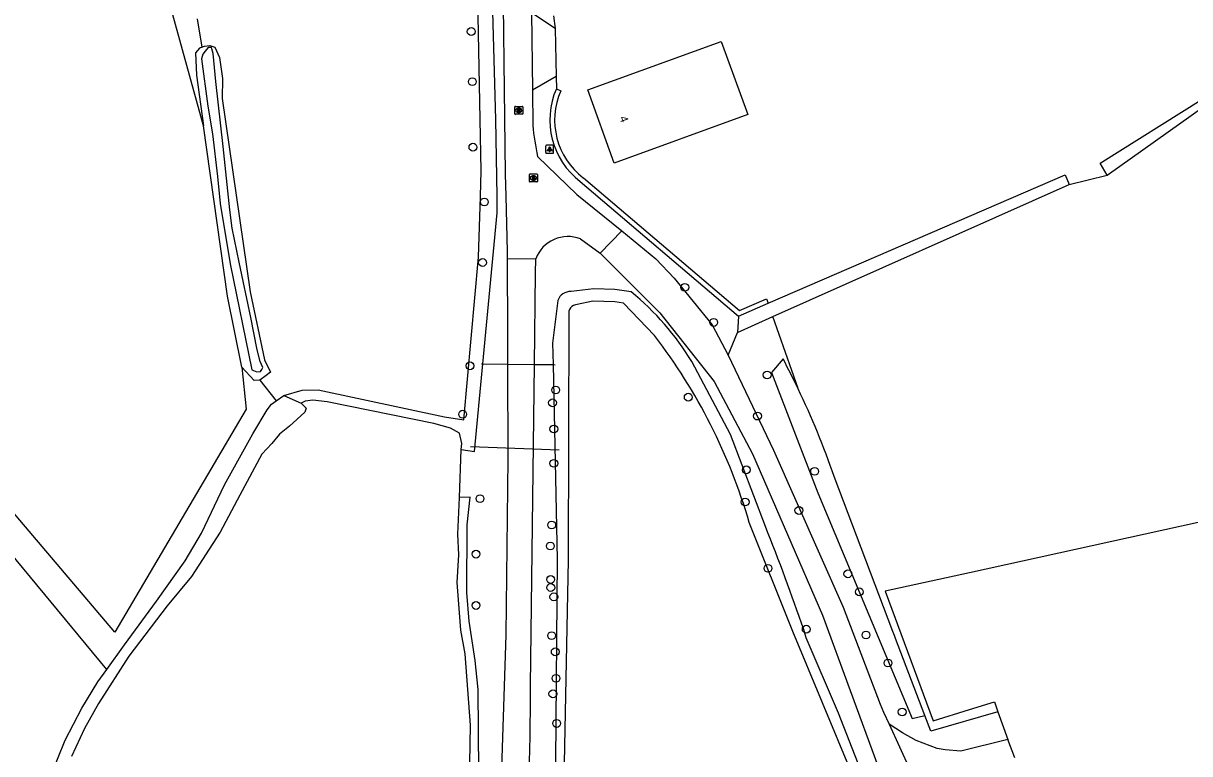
# Model space of a CAD drawing. Extents: x 163863 to 164644, y 379566 to 382155.
# Drawn here: x 164381.7 to 164527.5, y 381395.8 to 381487.2 of the extents above; entities that cross this region are included whole.
import ezdxf

# ---------------------------------------------------------------- set-up
doc = ezdxf.new("R2010")
doc.units = 0
for name, color, linetype in [('IMGEO_Boom', 7, 'Continuous'), ('IMGEO_Bouwland', 7, 'Continuous'), ('IMGEO_Brandkraan', 7, 'Continuous'), ('IMGEO_Duiker', 7, 'Continuous'), ('IMGEO_Grasland_agrarisch', 7, 'Continuous'), ('IMGEO_Grasland_overig', 7, 'Continuous'), ('IMGEO_Groenvoorziening', 7, 'Continuous'), ('IMGEO_Haag', 7, 'Continuous'), ('IMGEO_Lichtpunt', 7, 'Continuous'), ('IMGEO_Loofbos', 7, 'Continuous'), ('IMGEO_Pand', 7, 'Continuous'), ('IMGEO_Pand_nummerreeks', 7, 'Continuous'), ('IMGEO_Rijbaan_lokaal_gesloten', 7, 'Continuous'), ('IMGEO_Rijbaan_lokaal_onverhard', 7, 'Continuous'), ('IMGEO_Rioolput', 7, 'Continuous'), ('IMGEO_Voetpad_open', 7, 'Continuous'), ('IMGEO_Waterloop', 7, 'Continuous')]:
    doc.layers.add(name, color=color, linetype=linetype)

msp = doc.modelspace()

# ---------------------------------------------------------------- linework, layer by layer
at = {"layer": 'IMGEO_Boom'}
for centre in [(164437.72, 381486.12), (164437.86, 381479.85), (164437.93, 381471.66), (164439.36, 381464.81), (164439.13, 381457.24), (164464.41, 381454.14), (164468.02, 381449.75), (164437.56, 381444.32), (164474.7, 381443.18), (164448.27, 381441.3), (164447.88, 381439.7), (164464.84, 381440.4), (164436.65, 381438.27), (164473.49, 381438.04), (164448.04, 381436.43), (164448.05, 381432.13), (164472.1, 381431.32), (164480.63, 381431.13), (164438.82, 381427.72), (164471.95, 381427.29), (164478.67, 381426.24), (164447.78, 381424.42), (164447.61, 381421.79), (164438.32, 381420.78), (164474.8, 381419.01), (164447.64, 381417.61), (164484.79, 381418.31), (164447.66, 381416.6), (164486.22, 381416.06), (164438.32, 381414.36), (164448.04, 381415.44), (164479.59, 381411.39), (164447.77, 381410.59), (164487.06, 381410.66), (164448.22, 381408.56), (164489.8, 381407.16), (164448.32, 381405.25), (164447.92, 381403.31), (164491.58, 381401.04), (164448.4, 381399.61)]:
    msp.add_circle(centre, 0.489, dxfattribs=at)
at = {"layer": 'IMGEO_Bouwland'}
msp.add_lwpolyline([(164409.07, 381444.14), (164407.24, 381453.04), (164404.26, 381474.32)], dxfattribs=at)
at = {"layer": 'IMGEO_Brandkraan'}
for p, q in [((164445, 381467.39), (164445, 381468.24)), ((164445.07, 381468.31), (164445.92, 381468.31)), ((164445.92, 381467.31), (164445.07, 381467.31)), ((164445.48, 381468.09), (164445.51, 381468.09)), ((164445.51, 381467.53), (164445.48, 381467.53)), ((164446, 381468.24), (164446, 381467.39))]:
    msp.add_line(p, q, dxfattribs=at)
for points in [[(164445, 381467.39), (164445, 381468.24)], [(164445.07, 381468.31), (164445.92, 381468.31)], [(164445.92, 381467.31), (164445.07, 381467.31)], [(164445.34, 381468.01), (164445.34, 381467.61), (164445.56, 381467.61)], [(164445.58, 381468.01), (164445.34, 381468.01)], [(164445.52, 381467.93), (164445.47, 381467.93), (164445.47, 381467.86)], [(164445.47, 381467.86), (164445.52, 381467.86)], [(164445.53, 381467.78), (164445.47, 381467.78), (164445.47, 381467.7)], [(164445.47, 381467.7), (164445.53, 381467.7)], [(164446, 381468.24), (164446, 381467.39)]]:
    msp.add_lwpolyline(points, dxfattribs=at)
for centre, radius, start, end in [((164445.07, 381468.24), 0.0765, 91.552, 178.448), ((164445.07, 381468.24), 0.0765, 91.552, 178.448), ((164445.07, 381467.39), 0.0765, 181.552, 268.448), ((164445.07, 381467.39), 0.0765, 181.552, 268.448), ((164445.52, 381467.89), 0.0379, 267.8285, 90.9355), ((164445.53, 381467.74), 0.0404, 269.8759, 90.5077), ((164445.56, 381467.86), 0.251, 268.6676, 293.5347), ((164445.58, 381467.87), 0.145, 59.4692, 91.5367), ((164445.6, 381467.92), 0.0922, 285.5137, 58.1501), ((164445.61, 381467.72), 0.105, 301.3115, 78.989), ((164445.92, 381468.24), 0.0765, 1.552, 88.448), ((164445.92, 381468.24), 0.0765, 1.552, 88.448), ((164445.92, 381467.39), 0.0765, 271.552, 358.448), ((164445.92, 381467.39), 0.0765, 271.552, 358.448)]:
    msp.add_arc(centre, radius, start, end, dxfattribs=at)
for centre, major_axis, ratio, start_param, end_param in [((164445.48, 381467.81), (-0.387, 0.002), 0.722429, 4.712389, 7.853982), ((164445.51, 381467.81), (-0.39, 0.002), 0.717154, 1.570796, 4.712389)]:
    msp.add_ellipse(centre, major_axis=major_axis, ratio=ratio, start_param=start_param, end_param=end_param, dxfattribs=at)
at = {"layer": 'IMGEO_Duiker'}
for points in [[(164439.02, 381444.59), (164439.18, 381444.59), (164442.26, 381444.54), (164445.61, 381444.5), (164447.94, 381444.47), (164448.19, 381444.46)], [(164437.61, 381434.25), (164448.69, 381433.81)]]:
    msp.add_lwpolyline(points, dxfattribs=at)
at = {"layer": 'IMGEO_Grasland_agrarisch'}
for points in [[(164512.46, 381467.01), (164517.19, 381468.15)], [(164478.57, 381441.47), (164475.43, 381450.48)], [(164557.52, 381431.13), (164500, 381418.46), (164489.46, 381416.14), (164495.45, 381399.95), (164500, 381401.35), (164503.1, 381402.3), (164503.54, 381401.07)], [(164503.54, 381401.07), (164495.14, 381398.66), (164494.4, 381400.61)]]:
    msp.add_lwpolyline(points, dxfattribs=at)
at = {"layer": 'IMGEO_Grasland_overig'}
for points in [[(164409.07, 381444.14), (164409.6, 381438.92), (164393.19, 381411.03), (164380.14, 381426.39), (164361.95, 381448.81), (164345.91, 381468.69), (164324.9, 381495.18), (164300.88, 381524.96), (164285.02, 381541.92)], [(164392.18, 381406.36), (164355.54, 381450.6), (164307.96, 381511.18), (164292.08, 381530.61), (164282.94, 381540.64)], [(164404.26, 381474.32), (164397.81, 381497.74), (164374.92, 381491), (164348.35, 381518.62)], [(164404.03, 381484.15), (164403.76, 381484.04), (164403.25, 381483.47), (164403.38, 381480.67), (164404.26, 381474.32)], [(164411.28, 381442.54), (164410.57, 381442.48), (164409.07, 381444.14)]]:
    msp.add_lwpolyline(points, dxfattribs=at)
at = {"layer": 'IMGEO_Groenvoorziening'}
for points in [[(164447.99, 381488.08), (164448.2, 381486.51)], [(164448.33, 381480.51), (164448.37, 381478.97)], [(164469.83, 381445.64), (164471, 381448.5)], [(164436.26, 381427.88), (164436.48, 381433.86)], [(164503.54, 381401.07), (164504.8, 381397.62)]]:
    msp.add_lwpolyline(points, dxfattribs=at)
at = {"layer": 'IMGEO_Haag'}
for points in [[(164448.37, 381478.97), (164448.92, 381478.72)], [(164451.35, 381467.38), (164471.14, 381450.55)], [(164451.73, 381467.85), (164471.25, 381451.25), (164474.6, 381452.7), (164474.84, 381452.15)]]:
    msp.add_lwpolyline(points, dxfattribs=at)
for radius, start, end in [(9.66, 156.1754, 232.7263), (9.06, 156.1781, 232.8221)]:
    msp.add_arc((164457.2, 381475.06), radius, start, end, dxfattribs=at)
at = {"layer": 'IMGEO_Lichtpunt'}
for p, q in [((164447.02, 381471.8), (164447.02, 381470.99)), ((164447.02, 381471.8), (164447.02, 381470.99)), ((164447.92, 381471.9), (164447.12, 381471.9)), ((164447.92, 381471.9), (164447.12, 381471.9)), ((164448.02, 381470.99), (164448.02, 381471.8)), ((164448.02, 381470.99), (164448.02, 381471.8)), ((164447.12, 381470.9), (164447.92, 381470.9)), ((164447.12, 381470.9), (164447.92, 381470.9))]:
    msp.add_line(p, q, dxfattribs=at)
for points in [[(164447.4, 381471.46), (164447.43, 381471.44), (164447.25, 381471.17), (164447.21, 381471.2), (164447.4, 381471.46)], [(164447.5, 381471.42), (164447.55, 381471.42), (164447.55, 381471.09), (164447.5, 381471.09), (164447.5, 381471.42)], [(164447.61, 381471.44), (164447.65, 381471.46), (164447.83, 381471.2), (164447.79, 381471.17), (164447.61, 381471.44)]]:
    msp.add_lwpolyline(points, dxfattribs=at)
msp.add_circle((164447.52, 381471.6), 0.0994, dxfattribs=at)
for centre, start, end in [((164447.12, 381471.8), 90, 180), ((164447.12, 381471.8), 90, 180), ((164447.92, 381471.8), 0, 90), ((164447.92, 381471.8), 0, 90), ((164447.12, 381470.99), 180, 270), ((164447.12, 381470.99), 180, 270), ((164447.92, 381470.99), 270, 0), ((164447.92, 381470.99), 270, 360)]:
    msp.add_arc(centre, 0.0946, start, end, dxfattribs=at)
at = {"layer": 'IMGEO_Loofbos'}
for points in [[(164403.46, 381487.71), (164404.03, 381484.15)], [(164404.03, 381484.15), (164404.39, 381484.3), (164405.03, 381484.38), (164405.68, 381484.15), (164406.25, 381482.86), (164406.64, 381480.23), (164406.59, 381477.76), (164410.1, 381453.56), (164411.9, 381445.09), (164412.65, 381443.51), (164412.09, 381443.12), (164411.28, 381442.54)], [(164411.28, 381442.54), (164413.32, 381439.94)]]:
    msp.add_lwpolyline(points, dxfattribs=at)
at = {"layer": 'IMGEO_Pand'}
msp.add_lwpolyline([(164472.27, 381475.73), (164455.6, 381469.67), (164452.28, 381478.83), (164468.94, 381484.89), (164472.27, 381475.73)], dxfattribs=at)
at = {"layer": 'IMGEO_Rijbaan_lokaal_gesloten'}
for points in [[(164440.42, 381600.95), (164441.6, 381500), (164441.98, 381468.27), (164442.05, 381465.53), (164442.22, 381458.62), (164442.22, 381457.68)], [(164445.25, 381488.48), (164445.36, 381478.81)], [(164445.36, 381478.81), (164445.42, 381474.39)], [(164446.02, 381470.48), (164450.9, 381465.73), (164456.53, 381461.21)], [(164451.38, 381460.19), (164453.83, 381458.42)], [(164456.53, 381461.21), (164453.83, 381458.42)], [(164442.22, 381457.68), (164442.24, 381448.35), (164442.26, 381444.54), (164442.31, 381432.69), (164442.03, 381410.67), (164440.93, 381376.03), (164437.62, 381342.51), (164436.86, 381328.83), (164436.27, 381323.37), (164435.38, 381319.58), (164433.55, 381313.72), (164431.24, 381307.56), (164428.74, 381302.37)], [(164445.79, 381457.7), (164442.22, 381457.68)], [(164445.14, 381404.29), (164445.61, 381444.5), (164445.75, 381455.9), (164445.79, 381457.7)]]:
    msp.add_lwpolyline(points, dxfattribs=at)
for centre, radius, start, end in [((164479.34, 381477.6), 34.08, 185.4069, 192.0479), ((164449.81, 381456.2), 4.29, 68.4859, 159.4524), ((164127.19, 381404.33), 317.95, 355.4455, 359.9916)]:
    msp.add_arc(centre, radius, start, end, dxfattribs=at)
at = {"layer": 'IMGEO_Rijbaan_lokaal_onverhard'}
for points in [[(164456.53, 381461.21), (164460.78, 381457.7), (164463.09, 381455.28), (164467.82, 381449.45), (164469.83, 381445.64)], [(164453.83, 381458.42), (164461.3, 381450.96), (164468.06, 381442.36), (164472.89, 381433.3), (164481.62, 381413.16), (164488.52, 381394.29), (164489.58, 381392.13), (164490.06, 381391.38)], [(164469.83, 381445.64), (164475.49, 381433.77), (164484.2, 381414.14), (164488.82, 381402.01), (164489.26, 381401.03), (164489.95, 381399.53)], [(164489.95, 381399.53), (164492.54, 381393.86), (164495.51, 381388.98), (164495.77, 381388.57)], [(164504.8, 381397.62), (164498.9, 381396.14), (164496.96, 381396.31), (164495.95, 381396.49), (164493.32, 381397.48), (164491.62, 381398.45), (164489.95, 381399.53)], [(164505.66, 381395.29), (164504.8, 381397.62)]]:
    msp.add_lwpolyline(points, dxfattribs=at)
at = {"layer": 'IMGEO_Rioolput'}
for p, q in [((164443.16, 381475.84), (164443.16, 381476.69)), ((164443.24, 381476.77), (164444.09, 381476.77)), ((164443.65, 381476.55), (164443.68, 381476.55)), ((164443.67, 381475.99), (164443.65, 381475.99)), ((164444.16, 381476.69), (164444.16, 381475.84)), ((164444.09, 381475.77), (164443.24, 381475.77))]:
    msp.add_line(p, q, dxfattribs=at)
for points in [[(164443.16, 381475.84), (164443.16, 381476.69)], [(164443.24, 381476.77), (164444.09, 381476.77)], [(164443.75, 381476.46), (164443.5, 381476.47), (164443.5, 381476.07)], [(164443.5, 381476.07), (164443.62, 381476.07), (164443.62, 381476.23), (164443.64, 381476.23)], [(164443.68, 381476.39), (164443.62, 381476.39), (164443.62, 381476.3)], [(164443.62, 381476.3), (164443.68, 381476.3)], [(164443.68, 381476.2), (164443.75, 381476.07), (164443.89, 381476.07), (164443.83, 381476.19)], [(164444.16, 381476.69), (164444.16, 381475.84)], [(164444.09, 381475.77), (164443.24, 381475.77)]]:
    msp.add_lwpolyline(points, dxfattribs=at)
for centre, radius, start, end in [((164443.24, 381476.69), 0.0765, 91.552, 178.448), ((164443.24, 381476.69), 0.0765, 91.552, 178.448), ((164443.63, 381476.18), 0.0533, 26.0293, 88.6989), ((164443.68, 381476.29), 0.0964, 77.0061, 93.1865), ((164443.66, 381476.49), 0.19, 274.7715, 282.9687), ((164443.7, 381476.35), 0.0378, 276.6634, 79.6772), ((164443.75, 381476.36), 0.109, 350.3612, 89.416), ((164443.75, 381476.35), 0.112, 277.5842, 350.9817), ((164443.73, 381476.14), 0.108, 29.5134, 73.7905), ((164444.09, 381476.69), 0.0765, 1.552, 88.448), ((164444.09, 381476.69), 0.0765, 1.552, 88.448), ((164443.24, 381475.84), 0.0765, 181.552, 268.448), ((164443.24, 381475.84), 0.0765, 181.552, 268.448), ((164444.09, 381475.84), 0.0765, 271.552, 358.448), ((164444.09, 381475.84), 0.0765, 271.552, 358.448)]:
    msp.add_arc(centre, radius, start, end, dxfattribs=at)
for centre, major_axis, ratio, start_param, end_param in [((164443.65, 381476.27), (-0.387, 0.002), 0.722429, 4.712389, 7.853982), ((164443.67, 381476.27), (-0.39, 0.002), 0.717154, 1.570796, 4.712389)]:
    msp.add_ellipse(centre, major_axis=major_axis, ratio=ratio, start_param=start_param, end_param=end_param, dxfattribs=at)
at = {"layer": 'IMGEO_Voetpad_open'}
for points in [[(164448.2, 381486.51), (164445.25, 381488.48)], [(164448.2, 381486.51), (164448.33, 381480.51)], [(164448.33, 381480.51), (164445.36, 381478.81)]]:
    msp.add_lwpolyline(points, dxfattribs=at)
at = {"layer": 'IMGEO_Waterloop'}
for points in [[(164414.31, 381440.63), (164416.58, 381441.28), (164418.61, 381441.32), (164434.38, 381437.96), (164436.81, 381437.57), (164438.64, 381457.92), (164438.87, 381465.51), (164438.97, 381468.71), (164438.46, 381494.53)], [(164436.48, 381433.86), (164438.14, 381433.63), (164439.18, 381444.59), (164440.98, 381463.45), (164440.95, 381465.52), (164440.8, 381475.11), (164440.25, 381494.63), (164438.46, 381494.53)], [(164407.53, 381463.83), (164406.72, 381471.74), (164405.79, 381479.89), (164405.45, 381483.37), (164405.32, 381483.98), (164405.26, 381484.11), (164404.86, 381484.11), (164404.48, 381483.66), (164404.16, 381483.28), (164404.01, 381482.73), (164404.78, 381476.8), (164405.39, 381473.34), (164406.01, 381467.98), (164406.34, 381464.64), (164407.59, 381457.08), (164410.3, 381443.81), (164410.92, 381443.56), (164411.38, 381443.62), (164411.54, 381443.86), (164411.66, 381444.1), (164411.32, 381444.86), (164410.96, 381446.31), (164410.16, 381450.38), (164408.72, 381457.27), (164407.85, 381461.55), (164407.53, 381463.83)], [(164517.19, 381468.15), (164516.33, 381469.65), (164528.93, 381477.6), (164529.2, 381476.95)], [(164517.19, 381468.15), (164529.29, 381476.74), (164529.2, 381476.95)], [(164474.84, 381452.15), (164511.94, 381468.21), (164512.46, 381467.01)], [(164475.43, 381450.48), (164512.46, 381467.01)], [(164457.71, 381453.56), (164455.68, 381453.86), (164453.04, 381453.95), (164450.2, 381453.62)], [(164448.54, 381452.5), (164447.88, 381447.15), (164447.94, 381444.47), (164448.45, 381420.11), (164448.25, 381394.83), (164446.95, 381371.56), (164444.37, 381343.32)], [(164460.62, 381448.13), (164456.76, 381452.17), (164455.65, 381452.33), (164452.93, 381452.41), (164450.97, 381451.98)], [(164471.14, 381450.55), (164474.84, 381452.15)], [(164449.93, 381450.68), (164449.82, 381420.02), (164449.32, 381394.65), (164447.9, 381371.31), (164445.92, 381344.04), (164444.37, 381343.32)], [(164471.14, 381450.55), (164471, 381448.5)], [(164471, 381448.5), (164475.43, 381450.48)], [(164474.48, 381424.25), (164470.11, 381435.74), (164465.27, 381444.86)], [(164476.7, 381445.19), (164475.23, 381443.5), (164481.04, 381428.46), (164492.84, 381400.24), (164494.4, 381400.61)], [(164416.47, 381439.65), (164417.11, 381439.05), (164416.92, 381438.55), (164415.01, 381436.77), (164413.74, 381435.79), (164412.81, 381434.63), (164411.55, 381433.26), (164408.82, 381428.16), (164406.36, 381423.54), (164402.76, 381418), (164399.72, 381414.31), (164394.93, 381408.01), (164391.13, 381402.09), (164389.38, 381398.98), (164387.76, 381395.46)], [(164392.18, 381406.36), (164394.4, 381409.44), (164398.39, 381414.89), (164401.98, 381419.95), (164404, 381423.42), (164406.9, 381429.46), (164410.43, 381435.84), (164412.2, 381438.82), (164412.76, 381439.55), (164413.32, 381439.94)], [(164413.32, 381439.94), (164414.31, 381440.63)], [(164414.31, 381440.63), (164416.47, 381439.65)], [(164436.48, 381433.86), (164436.54, 381434.61), (164436.27, 381435.91), (164435.14, 381436.53), (164433.06, 381437.13), (164419.72, 381439.84), (164417.94, 381440.02), (164416.98, 381439.9), (164416.47, 381439.65)], [(164494.4, 381400.61), (164490.75, 381410.23), (164490.61, 381410.59), (164490.42, 381411.1), (164483.06, 381430.48)], [(164423.74, 381298.57), (164430.45, 381312.12), (164432.38, 381317.5), (164434.01, 381324.36), (164434.72, 381330), (164434.91, 381333.02), (164434.92, 381340.08), (164434.38, 381351.46), (164434.48, 381356.02), (164434.81, 381360.28), (164438.01, 381382.93), (164438.49, 381387.99), (164438.66, 381393.57), (164438.58, 381403.85), (164438.23, 381407.47), (164437.47, 381412.38), (164437.16, 381415.96), (164437.21, 381424.46), (164437.58, 381427.9), (164436.26, 381427.88)], [(164434.19, 381336.08), (164433.57, 381357.04), (164434.19, 381362.6), (164436.96, 381381.93), (164437.41, 381387.54), (164437.63, 381399.41), (164436.95, 381408.32), (164436.41, 381411.28), (164435.98, 381417.22), (164436.15, 381420.7), (164436.03, 381423.26), (164436.26, 381427.88)], [(164485.33, 381393.26), (164477.93, 381411.1), (164472.47, 381424.73)], [(164485.33, 381393.26), (164485.77, 381393.51), (164486.37, 381393.84), (164483.6, 381400.91), (164479.59, 381410.3), (164479.27, 381411.35)], [(164387.17, 381367.35), (164385.24, 381370.99), (164383.54, 381375.27), (164382.71, 381380.71), (164383.19, 381384.77), (164383.93, 381388.75), (164385.23, 381393.19), (164386.96, 381397.52), (164389.07, 381401.5), (164391.05, 381404.79), (164392.18, 381406.36)]]:
    msp.add_lwpolyline(points, dxfattribs=at)
for centre, radius, start, end in [((164450.14, 381451.91), 1.71, 88.1681, 159.72), ((164436.5, 381427.49), 33.61, 31.1211, 50.8769), ((164450.97, 381450.91), 1.07, 90.0825, 192.4044), ((164404.37, 381404.95), 70.91, 16.1952, 37.5056), ((164385.55, 381397.06), 103.07, 25.5187, 27.833), ((164385.47, 381397.01), 103.17, 18.9285, 25.5241), ((164227.29, 381325.01), 266.36, 18.9147, 21.8737)]:
    msp.add_arc(centre, radius, start, end, dxfattribs=at)

# ---------------------------------------------------------------- texts
at = {"layer": 'IMGEO_Pand_nummerreeks'}
msp.add_text('4', height=1, rotation=289.932, dxfattribs=at).set_placement((164456.22, 381475.36))

doc.saveas('drawing.dxf')
